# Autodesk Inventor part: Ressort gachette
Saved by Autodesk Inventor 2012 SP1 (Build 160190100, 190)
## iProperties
Created: 2014-12
Part Number: Ressort gachette
Material: Default
Document SubType Name: Modeling
Designer: Bruno
Density: 1 g/cm^3
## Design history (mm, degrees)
node "Ressort gachette1"
node "Ressort gachette"
node "Base1"
